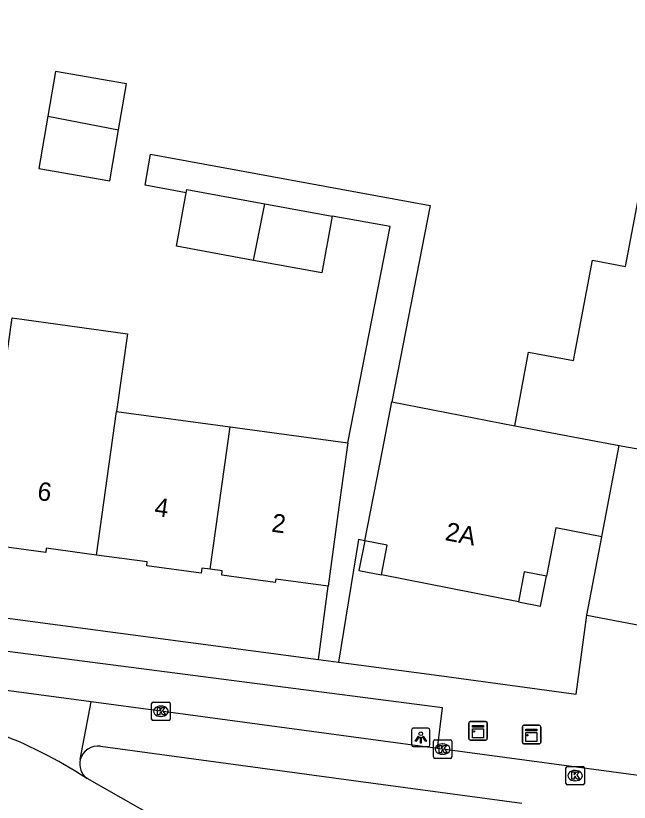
# Model space of a CAD drawing. Extents: x 161402 to 161933, y 381650 to 382313.
# Drawn here: x 161793.88 to 161827.22, y 381673.98 to 381716.7 of the extents above; entities that cross this region are included whole.
import ezdxf

# ---------------------------------------------------------------- set-up
doc = ezdxf.new("R2010")
doc.units = 0
for name, color, linetype in [('IMGEO_Fietspad_gesloten', 7, 'Continuous'), ('IMGEO_Kast', 7, 'Continuous'), ('IMGEO_Kolk', 7, 'Continuous'), ('IMGEO_Lichtpunt', 7, 'Continuous'), ('IMGEO_Pand', 7, 'Continuous'), ('IMGEO_Pand_nummerreeks', 7, 'Continuous'), ('IMGEO_Pand_overbouw', 7, 'Continuous'), ('IMGEO_Rijbaan_lokaal_gesloten', 7, 'Continuous'), ('IMGEO_Rijbaan_lokaal_open', 7, 'Continuous'), ('IMGEO_Voetpad_open', 7, 'Continuous')]:
    doc.layers.add(name, color=color, linetype=linetype)

msp = doc.modelspace()

# ---------------------------------------------------------------- linework, layer by layer
at = {"layer": 'IMGEO_Fietspad_gesloten'}
for points in [[(161816.794, 381676.903), (161801.769, 381678.925), (161797.978, 381679.434)], [(161798.491, 381677.029), (161812.233, 381675.169), (161821.38, 381673.928)], [(161828.401, 381675.346), (161817.079, 381676.869), (161816.794, 381676.903)]]:
    msp.add_lwpolyline(points, dxfattribs=at)
msp.add_arc((161798.345, 381676.055), 0.985, 81.4794, 165.5876, dxfattribs=at)
at = {"layer": 'IMGEO_Kast'}
for p, q in [((161818.502, 381677.44), (161818.502, 381678.281)), ((161818.502, 381678.281), (161818.502, 381677.44)), ((161818.577, 381678.365), (161819.418, 381678.365)), ((161819.418, 381678.365), (161818.577, 381678.365)), ((161819.502, 381678.29), (161819.502, 381677.449)), ((161819.502, 381677.449), (161819.502, 381678.29)), ((161821.412, 381677.238), (161821.412, 381678.079)), ((161821.412, 381678.079), (161821.412, 381677.238)), ((161821.487, 381678.163), (161822.328, 381678.163)), ((161822.328, 381678.163), (161821.487, 381678.163)), ((161822.412, 381678.088), (161822.412, 381677.247)), ((161822.412, 381677.247), (161822.412, 381678.088)), ((161819.427, 381677.365), (161818.586, 381677.365)), ((161818.586, 381677.365), (161819.427, 381677.365)), ((161822.337, 381677.163), (161821.496, 381677.163)), ((161821.496, 381677.163), (161822.337, 381677.163))]:
    msp.add_line(p, q, dxfattribs=at)
for points in [[(161818.697, 381678.155), (161819.297, 381678.155), (161819.297, 381678.07), (161818.697, 381678.07), (161818.697, 381678.155)], [(161818.697, 381677.98), (161819.297, 381677.98), (161819.297, 381677.491), (161818.697, 381677.491), (161818.697, 381677.98)], [(161821.607, 381677.953), (161822.207, 381677.953), (161822.207, 381677.868), (161821.607, 381677.868), (161821.607, 381677.953)], [(161821.607, 381677.778), (161822.207, 381677.778), (161822.207, 381677.289), (161821.607, 381677.289), (161821.607, 381677.778)]]:
    msp.add_lwpolyline(points, dxfattribs=at)
for centre in [(161818.781, 381677.829), (161821.691, 381677.627)]:
    msp.add_circle(centre, 0.0377, dxfattribs=at)
for centre, start, end in [((161818.58, 381678.287), 92.4484, 184.2845), ((161818.58, 381678.287), 92.4484, 184.2845), ((161819.424, 381678.287), 2.4484, 94.2845), ((161819.424, 381678.287), 2.4484, 94.2845), ((161821.49, 381678.085), 92.4484, 184.2845), ((161821.49, 381678.085), 92.4484, 184.2845), ((161822.334, 381678.085), 2.4484, 94.2845), ((161822.334, 381678.085), 2.4484, 94.2845), ((161818.58, 381677.443), 182.4484, 274.2845), ((161818.58, 381677.443), 182.4484, 274.2845), ((161819.424, 381677.443), 272.4484, 4.2845), ((161819.424, 381677.443), 272.4484, 4.2845), ((161821.49, 381677.241), 182.4484, 274.2845), ((161821.49, 381677.241), 182.4484, 274.2845), ((161822.334, 381677.241), 272.4484, 4.2845), ((161822.334, 381677.241), 272.4484, 4.2845)]:
    msp.add_arc(centre, 0.0779, start, end, dxfattribs=at)
at = {"layer": 'IMGEO_Kolk'}
for p, q in [((161801.268, 381678.499), (161801.268, 381679.351)), ((161801.343, 381679.425), (161802.195, 381679.425)), ((161801.756, 381679.205), (161801.781, 381679.205)), ((161802.269, 381679.351), (161802.269, 381678.499)), ((161801.779, 381678.645), (161801.754, 381678.645)), ((161802.195, 381678.425), (161801.343, 381678.425)), ((161816.653, 381677.369), (161817.505, 381677.369)), ((161816.578, 381676.443), (161816.578, 381677.295)), ((161817.066, 381677.149), (161817.091, 381677.149)), ((161817.579, 381677.295), (161817.579, 381676.443)), ((161817.089, 381676.589), (161817.064, 381676.589)), ((161817.505, 381676.369), (161816.653, 381676.369)), ((161823.78, 381675.004), (161823.78, 381675.856)), ((161823.855, 381675.93), (161824.707, 381675.93)), ((161824.268, 381675.71), (161824.293, 381675.71)), ((161824.781, 381675.856), (161824.781, 381675.004)), ((161824.707, 381674.93), (161823.855, 381674.93)), ((161824.291, 381675.15), (161824.266, 381675.15))]:
    msp.add_line(p, q, dxfattribs=at)
for points in [[(161801.268, 381678.499), (161801.268, 381679.351)], [(161801.343, 381679.425), (161802.195, 381679.425)], [(161801.589, 381679.125), (161801.712, 381679.125), (161801.712, 381678.974), (161801.842, 381679.125), (161802.006, 381679.125), (161801.86, 381678.974), (161802.013, 381678.725), (161801.861, 381678.725), (161801.776, 381678.889), (161801.712, 381678.822), (161801.712, 381678.725), (161801.589, 381678.725), (161801.589, 381679.125)], [(161802.269, 381679.351), (161802.269, 381678.499)], [(161802.195, 381678.425), (161801.343, 381678.425)], [(161816.653, 381677.369), (161817.505, 381677.369)], [(161816.578, 381676.443), (161816.578, 381677.295)], [(161816.899, 381677.069), (161817.022, 381677.069), (161817.022, 381676.918), (161817.152, 381677.069), (161817.316, 381677.069), (161817.17, 381676.918), (161817.323, 381676.669), (161817.171, 381676.669), (161817.086, 381676.833), (161817.022, 381676.766), (161817.022, 381676.669), (161816.899, 381676.669), (161816.899, 381677.069)], [(161817.579, 381677.295), (161817.579, 381676.443)], [(161817.505, 381676.369), (161816.653, 381676.369)], [(161823.78, 381675.004), (161823.78, 381675.856)], [(161823.855, 381675.93), (161824.707, 381675.93)], [(161824.781, 381675.856), (161824.781, 381675.004)], [(161824.101, 381675.63), (161824.224, 381675.63), (161824.224, 381675.479), (161824.354, 381675.63), (161824.518, 381675.63), (161824.372, 381675.479), (161824.525, 381675.23), (161824.373, 381675.23), (161824.288, 381675.394), (161824.224, 381675.327), (161824.224, 381675.23), (161824.101, 381675.23), (161824.101, 381675.63)], [(161824.707, 381674.93), (161823.855, 381674.93)]]:
    msp.add_lwpolyline(points, dxfattribs=at)
for centre, start, end in [((161801.345, 381679.349), 91.552, 178.448), ((161801.345, 381679.349), 91.552, 178.448), ((161802.193, 381679.349), 1.552, 88.448), ((161802.193, 381679.349), 1.552, 88.448), ((161801.345, 381678.501), 181.552, 268.448), ((161801.345, 381678.501), 181.552, 268.448), ((161802.193, 381678.501), 271.552, 358.448), ((161802.193, 381678.501), 271.552, 358.448), ((161816.655, 381677.293), 91.552, 178.448), ((161816.655, 381677.293), 91.552, 178.448), ((161817.503, 381677.293), 1.552, 88.448), ((161817.503, 381677.293), 1.552, 88.448), ((161816.655, 381676.445), 181.552, 268.448), ((161816.655, 381676.445), 181.552, 268.448), ((161817.503, 381676.445), 271.552, 358.448), ((161817.503, 381676.445), 271.552, 358.448), ((161823.857, 381675.854), 91.552, 178.448), ((161823.857, 381675.854), 91.552, 178.448), ((161824.705, 381675.854), 1.552, 88.448), ((161824.705, 381675.854), 1.552, 88.448), ((161823.857, 381675.006), 181.552, 268.448), ((161823.857, 381675.006), 181.552, 268.448), ((161824.705, 381675.006), 271.552, 358.448), ((161824.705, 381675.006), 271.552, 358.448)]:
    msp.add_arc(centre, 0.0765, start, end, dxfattribs=at)
for centre, major_axis, ratio, start_param, end_param in [((161801.755, 381678.925), (-0.387, 0.002), 0.722429, 4.712389, 7.853982), ((161801.78, 381678.925), (-0.39, 0.002), 0.717154, 1.570796, 4.712389), ((161817.065, 381676.869), (-0.387, 0.002), 0.722429, 4.712389, 7.853982), ((161817.09, 381676.869), (-0.39, 0.002), 0.717154, 1.570796, 4.712389), ((161824.267, 381675.43), (-0.387, 0.002), 0.722429, 4.712389, 7.853982), ((161824.292, 381675.43), (-0.39, 0.002), 0.717154, 1.570796, 4.712389)]:
    msp.add_ellipse(centre, major_axis=major_axis, ratio=ratio, start_param=start_param, end_param=end_param, dxfattribs=at)
at = {"layer": 'IMGEO_Lichtpunt'}
for p, q in [((161815.393, 381677.908), (161815.393, 381677.101)), ((161815.393, 381677.908), (161815.393, 381677.101)), ((161816.295, 381678.003), (161815.487, 381678.003)), ((161816.295, 381678.003), (161815.487, 381678.003)), ((161816.389, 381677.101), (161816.389, 381677.908)), ((161816.389, 381677.101), (161816.389, 381677.908)), ((161815.487, 381677.007), (161816.295, 381677.007)), ((161815.487, 381677.007), (161816.295, 381677.007))]:
    msp.add_line(p, q, dxfattribs=at)
for points in [[(161815.767, 381677.572), (161815.806, 381677.544), (161815.618, 381677.282), (161815.58, 381677.309), (161815.767, 381677.572)], [(161815.869, 381677.524), (161815.916, 381677.524), (161815.916, 381677.202), (161815.869, 381677.202), (161815.869, 381677.524)], [(161815.979, 381677.544), (161816.017, 381677.571), (161816.204, 381677.309), (161816.165, 381677.281), (161815.979, 381677.544)]]:
    msp.add_lwpolyline(points, dxfattribs=at)
msp.add_circle((161815.892, 381677.706), 0.0994, dxfattribs=at)
for centre, start, end in [((161815.487, 381677.908), 90, 180), ((161815.487, 381677.908), 90, 180), ((161816.295, 381677.908), 0, 90), ((161816.295, 381677.908), 0, 90), ((161815.487, 381677.101), 180, 270), ((161815.487, 381677.101), 180, 270), ((161816.295, 381677.101), 270, 0), ((161816.295, 381677.101), 270, 360)]:
    msp.add_arc(centre, 0.0946, start, end, dxfattribs=at)
at = {"layer": 'IMGEO_Pand'}
for points in [[(161820.996, 381694.433), (161821.755, 381698.436), (161824.188, 381697.974), (161825.224, 381703.428), (161827.019, 381703.087), (161830.821, 381723.103), (161823.085, 381724.572), (161823.785, 381728.257), (161831.52, 381726.788), (161832.066, 381729.665), (161840.41, 381728.097), (161845.322, 381727.164)], [(161799.468, 381710.507), (161799.901, 381713.004), (161796.043, 381713.673), (161795.624, 381711.251)], [(161795.624, 381711.251), (161795.13, 381708.402), (161798.988, 381707.734), (161799.468, 381710.507)], [(161795.624, 381711.251), (161799.468, 381710.507)], [(161803.143, 381707.088), (161803.177, 381707.272), (161807.418, 381706.495)], [(161806.799, 381703.413), (161802.611, 381704.18), (161803.143, 381707.088)], [(161806.799, 381703.413), (161807.418, 381706.495)], [(161807.418, 381706.495), (161811.08, 381705.825)], [(161811.08, 381705.825), (161810.513, 381702.732), (161806.799, 381703.413)], [(161793.095, 381696.061), (161793.69, 381700.304), (161799.95, 381699.426), (161799.359, 381695.212)], [(161812.847, 381688.187), (161813.804, 381693.095), (161814.319, 381695.735)], [(161814.319, 381695.735), (161820.996, 381694.433)], [(161798.265, 381687.412), (161799.359, 381695.212)], [(161799.359, 381695.212), (161805.528, 381694.375)], [(161804.442, 381686.636), (161805.528, 381694.375)], [(161805.528, 381694.375), (161811.92, 381693.508)], [(161820.996, 381694.433), (161826.668, 381693.365)], [(161811.92, 381693.508), (161811.536, 381690.676), (161810.864, 381685.721)], [(161825.725, 381688.406), (161825.745, 381688.512), (161826.668, 381693.365)], [(161826.668, 381693.365), (161836.743, 381691.565)], [(161825.725, 381688.406), (161823.234, 381688.891), (161822.721, 381686.261), (161821.514, 381686.497), (161821.198, 381684.877), (161813.758, 381686.328), (161814.074, 381687.948), (161812.847, 381688.187)], [(161798.265, 381687.412), (161795.543, 381687.782), (161795.51, 381687.543), (161792.563, 381687.942), (161792.6, 381688.213), (161792.005, 381688.294)], [(161824.917, 381684.151), (161825.725, 381688.406)], [(161804.442, 381686.636), (161803.987, 381686.698), (161803.951, 381686.434), (161801.004, 381686.834), (161801.031, 381687.037), (161798.265, 381687.412)], [(161810.864, 381685.721), (161808.013, 381686.108), (161807.987, 381685.916), (161805.076, 381686.311), (161805.108, 381686.546), (161804.442, 381686.636)], [(161824.917, 381684.151), (161830.531, 381683.085), (161830.604, 381683.472), (161835.307, 381682.579)]]:
    msp.add_lwpolyline(points, dxfattribs=at)
at = {"layer": 'IMGEO_Pand_overbouw'}
for points in [[(161813.758, 381686.328), (161814.074, 381687.948), (161812.847, 381688.187), (161812.531, 381686.567)], [(161822.721, 381686.261), (161821.514, 381686.497), (161821.198, 381684.877), (161822.405, 381684.642)]]:
    msp.add_lwpolyline(points, close=True, dxfattribs=at)
at = {"layer": 'IMGEO_Rijbaan_lokaal_gesloten'}
for points in [[(161797.978, 381679.434), (161783.474, 381681.383), (161780.28, 381681.817)], [(161797.391, 381676.3), (161797.978, 381679.434)]]:
    msp.add_lwpolyline(points, dxfattribs=at)
for centre, radius, start, end in [((161783.897, 381654.039), 25.352, 56.8562, 69.7711), ((161798.344, 381676.056), 0.984, 165.6492, 233.4336)]:
    msp.add_arc(centre, radius, start, end, dxfattribs=at)
at = {"layer": 'IMGEO_Rijbaan_lokaal_open'}
msp.add_lwpolyline([(161811.537, 381667.526), (161803.433, 381672.055), (161797.758, 381675.266)], dxfattribs=at)
at = {"layer": 'IMGEO_Voetpad_open'}
for points in [[(161803.143, 381707.088), (161800.916, 381707.496), (161801.214, 381709.179), (161816.398, 381706.393), (161814.319, 381695.735)], [(161811.92, 381693.508), (161814.221, 381705.25), (161811.08, 381705.825)], [(161812.847, 381688.187), (161812.504, 381688.254), (161811.416, 381681.599)], [(161781.286, 381685.605), (161785.387, 381685.06), (161810.335, 381681.743)], [(161810.335, 381681.743), (161810.864, 381685.721)], [(161816.794, 381676.903), (161817.073, 381679.111), (161780.562, 381683.829), (161780.28, 381681.817)], [(161811.416, 381681.599), (161816.889, 381680.871), (161824.343, 381679.854), (161824.917, 381684.151)], [(161810.335, 381681.743), (161811.416, 381681.599)]]:
    msp.add_lwpolyline(points, dxfattribs=at)

# ---------------------------------------------------------------- texts
at = {"layer": 'IMGEO_Pand_nummerreeks'}
for s, rotation, p in [('6', 352.2841, (161795.019, 381690.411)), ('4', 352.2841, (161801.383, 381689.549)), ('2', 352.2841, (161807.745, 381688.687)), ('2A', 348.9643, (161817.171, 381688.23))]:
    msp.add_text(s, height=1, rotation=rotation, dxfattribs=at).set_placement(p)

doc.saveas('drawing.dxf')
